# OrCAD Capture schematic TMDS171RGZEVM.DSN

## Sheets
1 P08:  TUSB3410: size B; title: TMDS171RGZEVM, TUSB3410; rev: A.0; company: Texas Instruments, CIS/ICP; note: GAGGIA.DSN
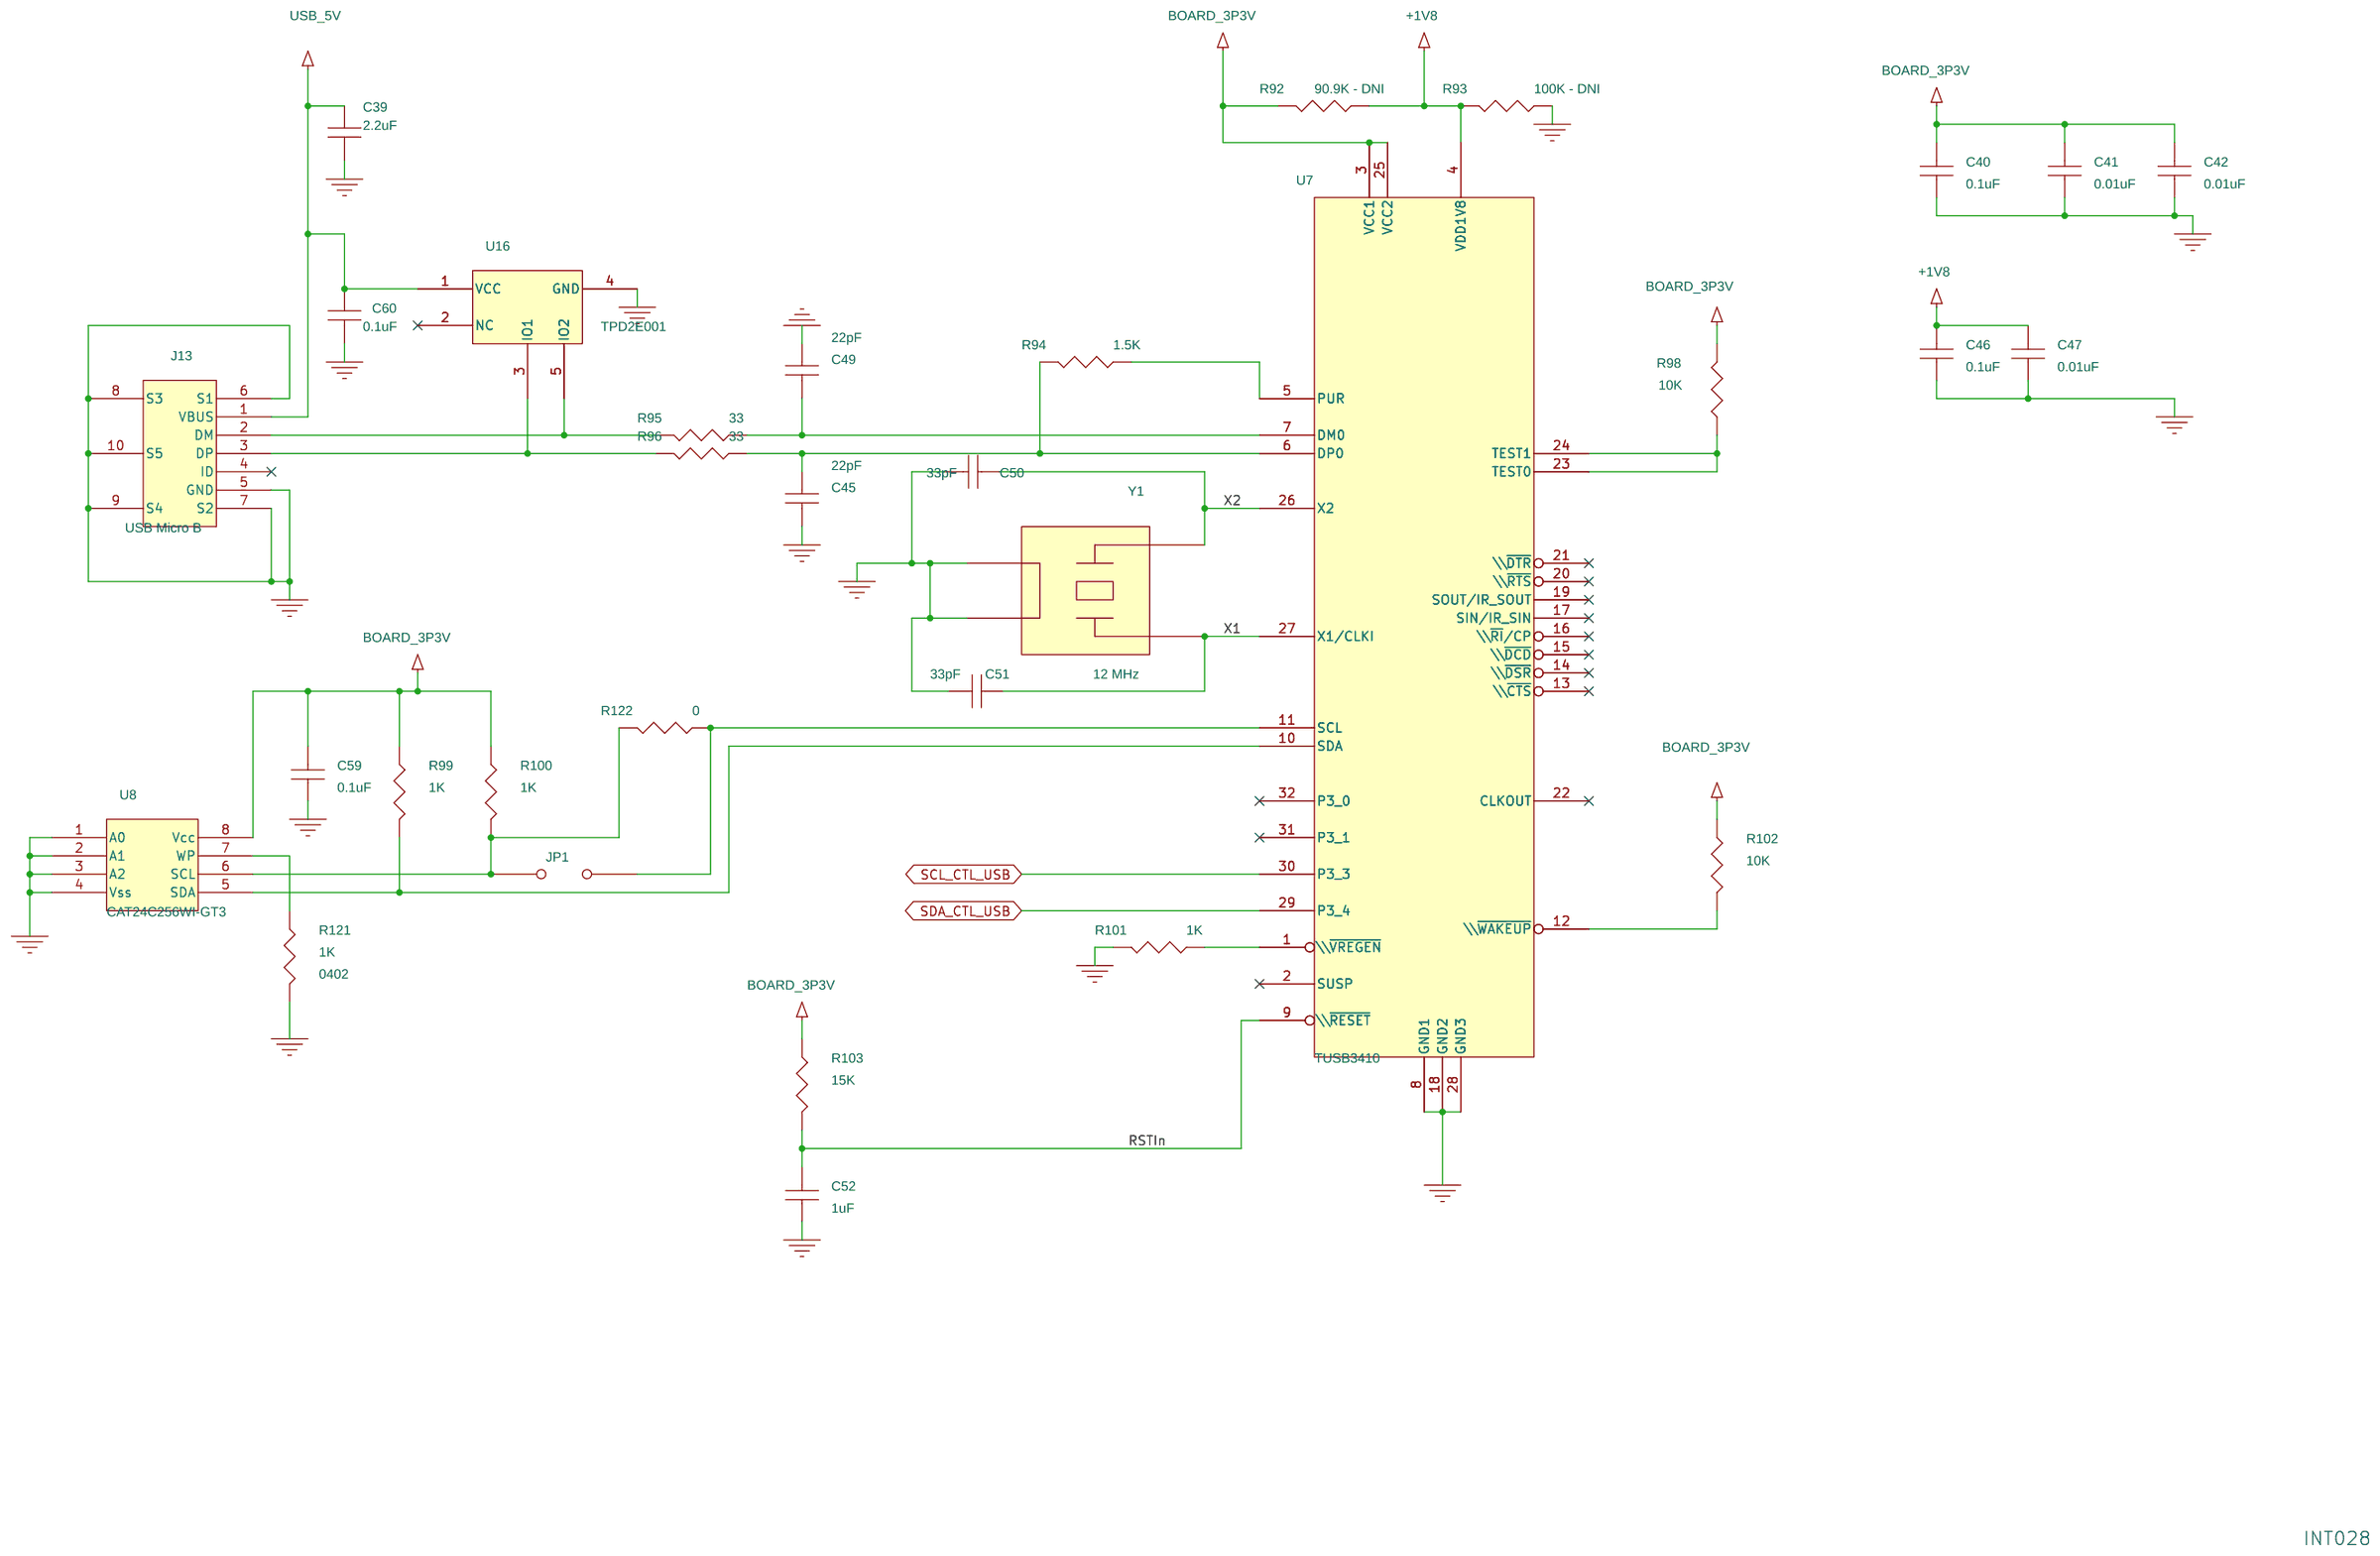
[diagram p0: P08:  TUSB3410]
2 P06:  RESET: size A; title: TMDS171RGZEVM, RESET
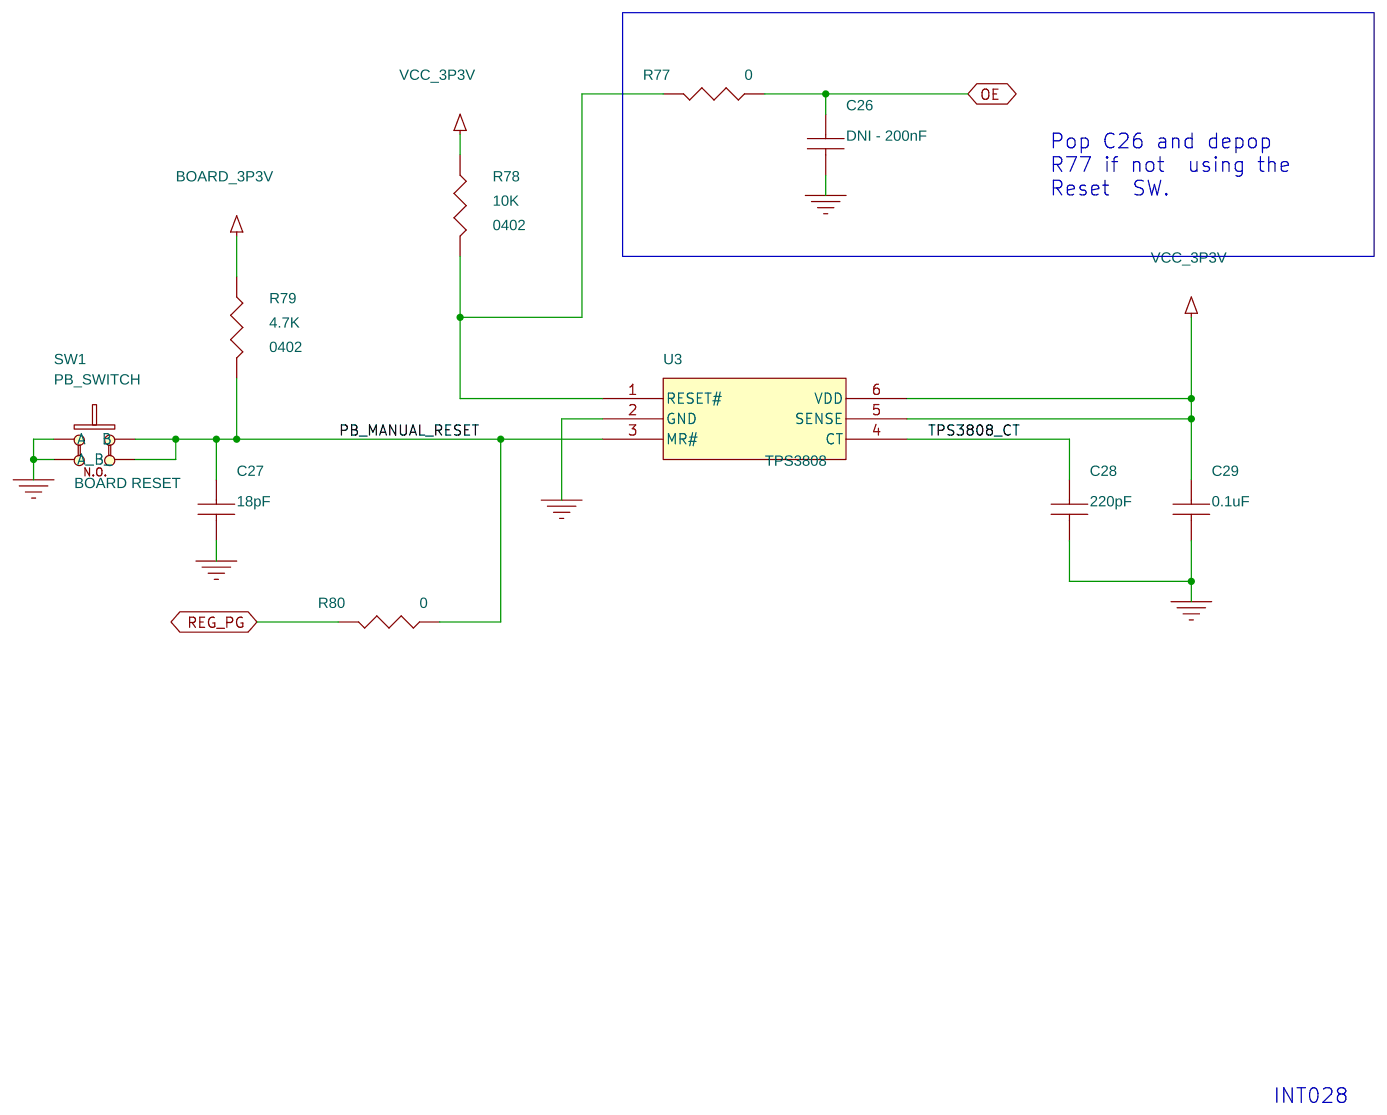
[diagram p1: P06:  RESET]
3 P01:  TITLE: size A; title: TMDS171RGZEVM
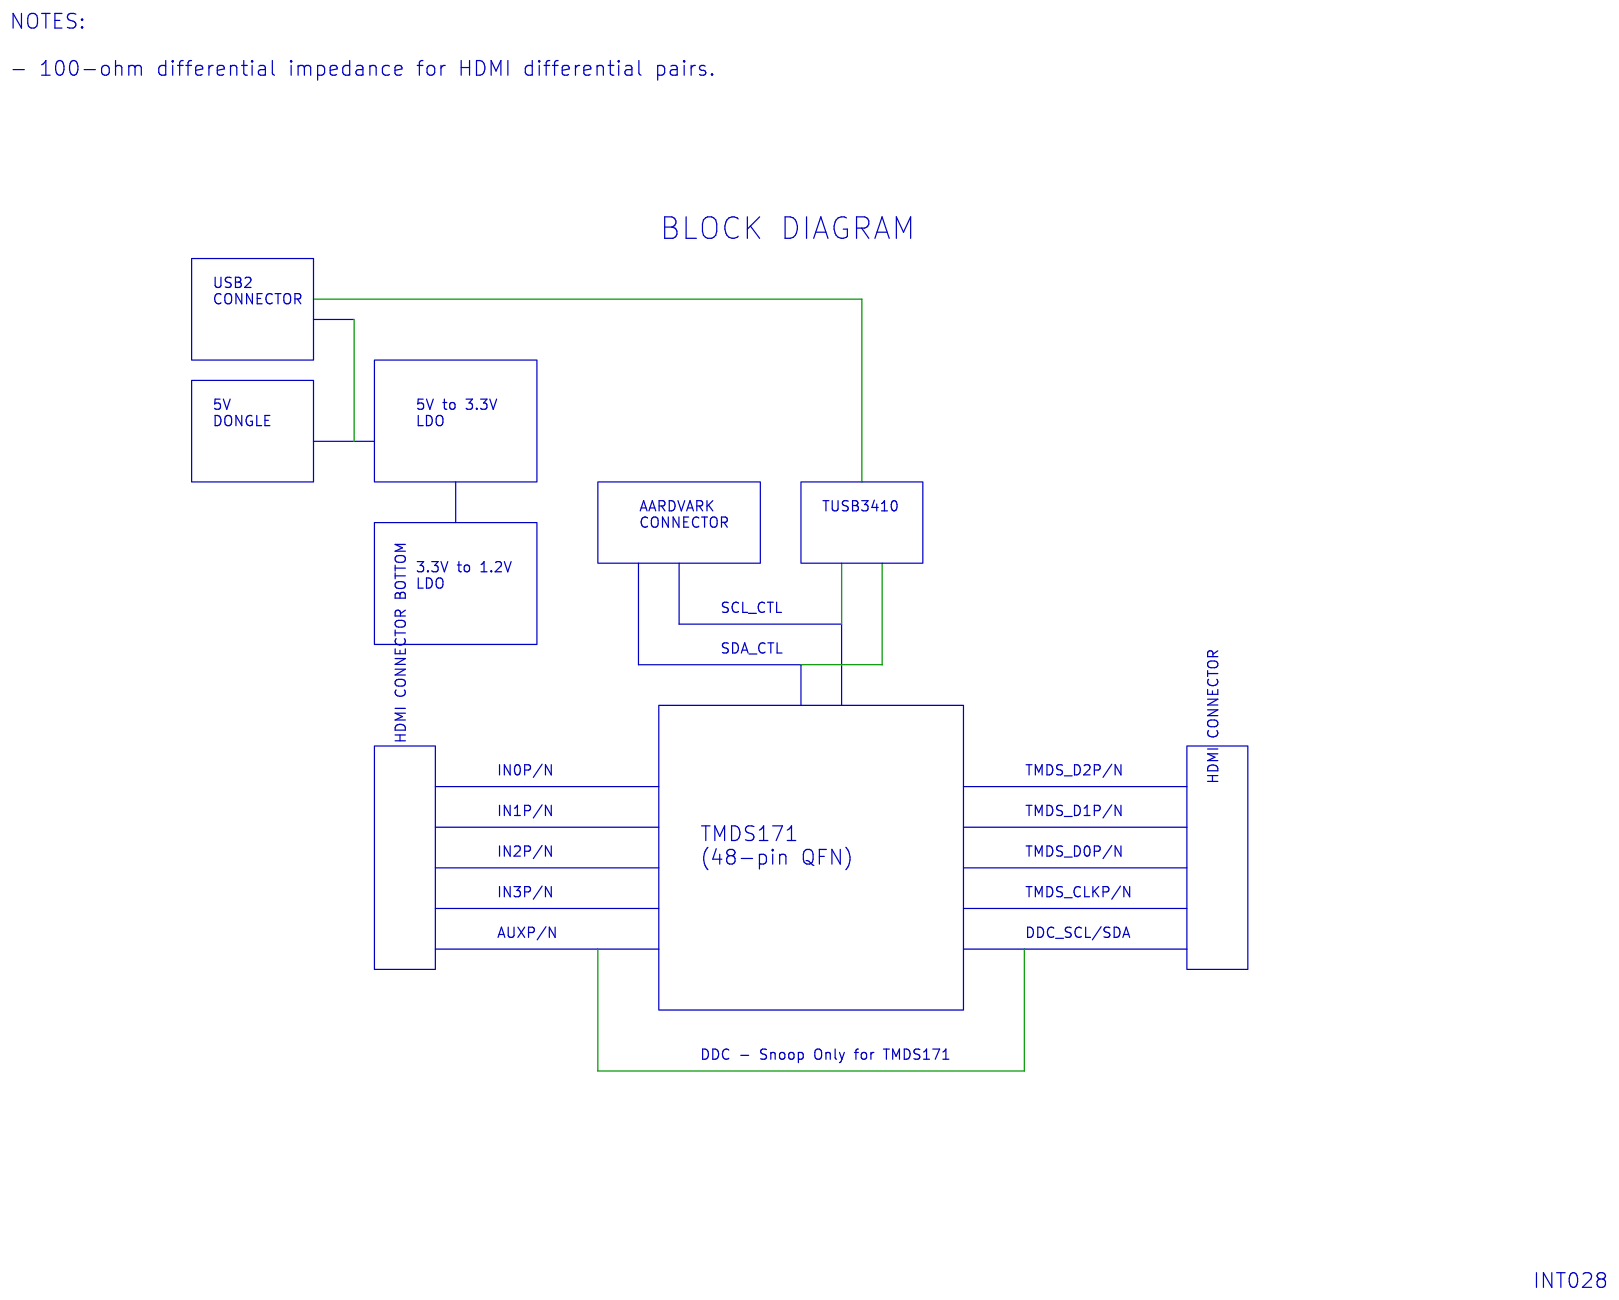
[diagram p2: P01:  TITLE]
4 P07:  POWER: size B; title: TMDS171RGZEVM, REGULATORS
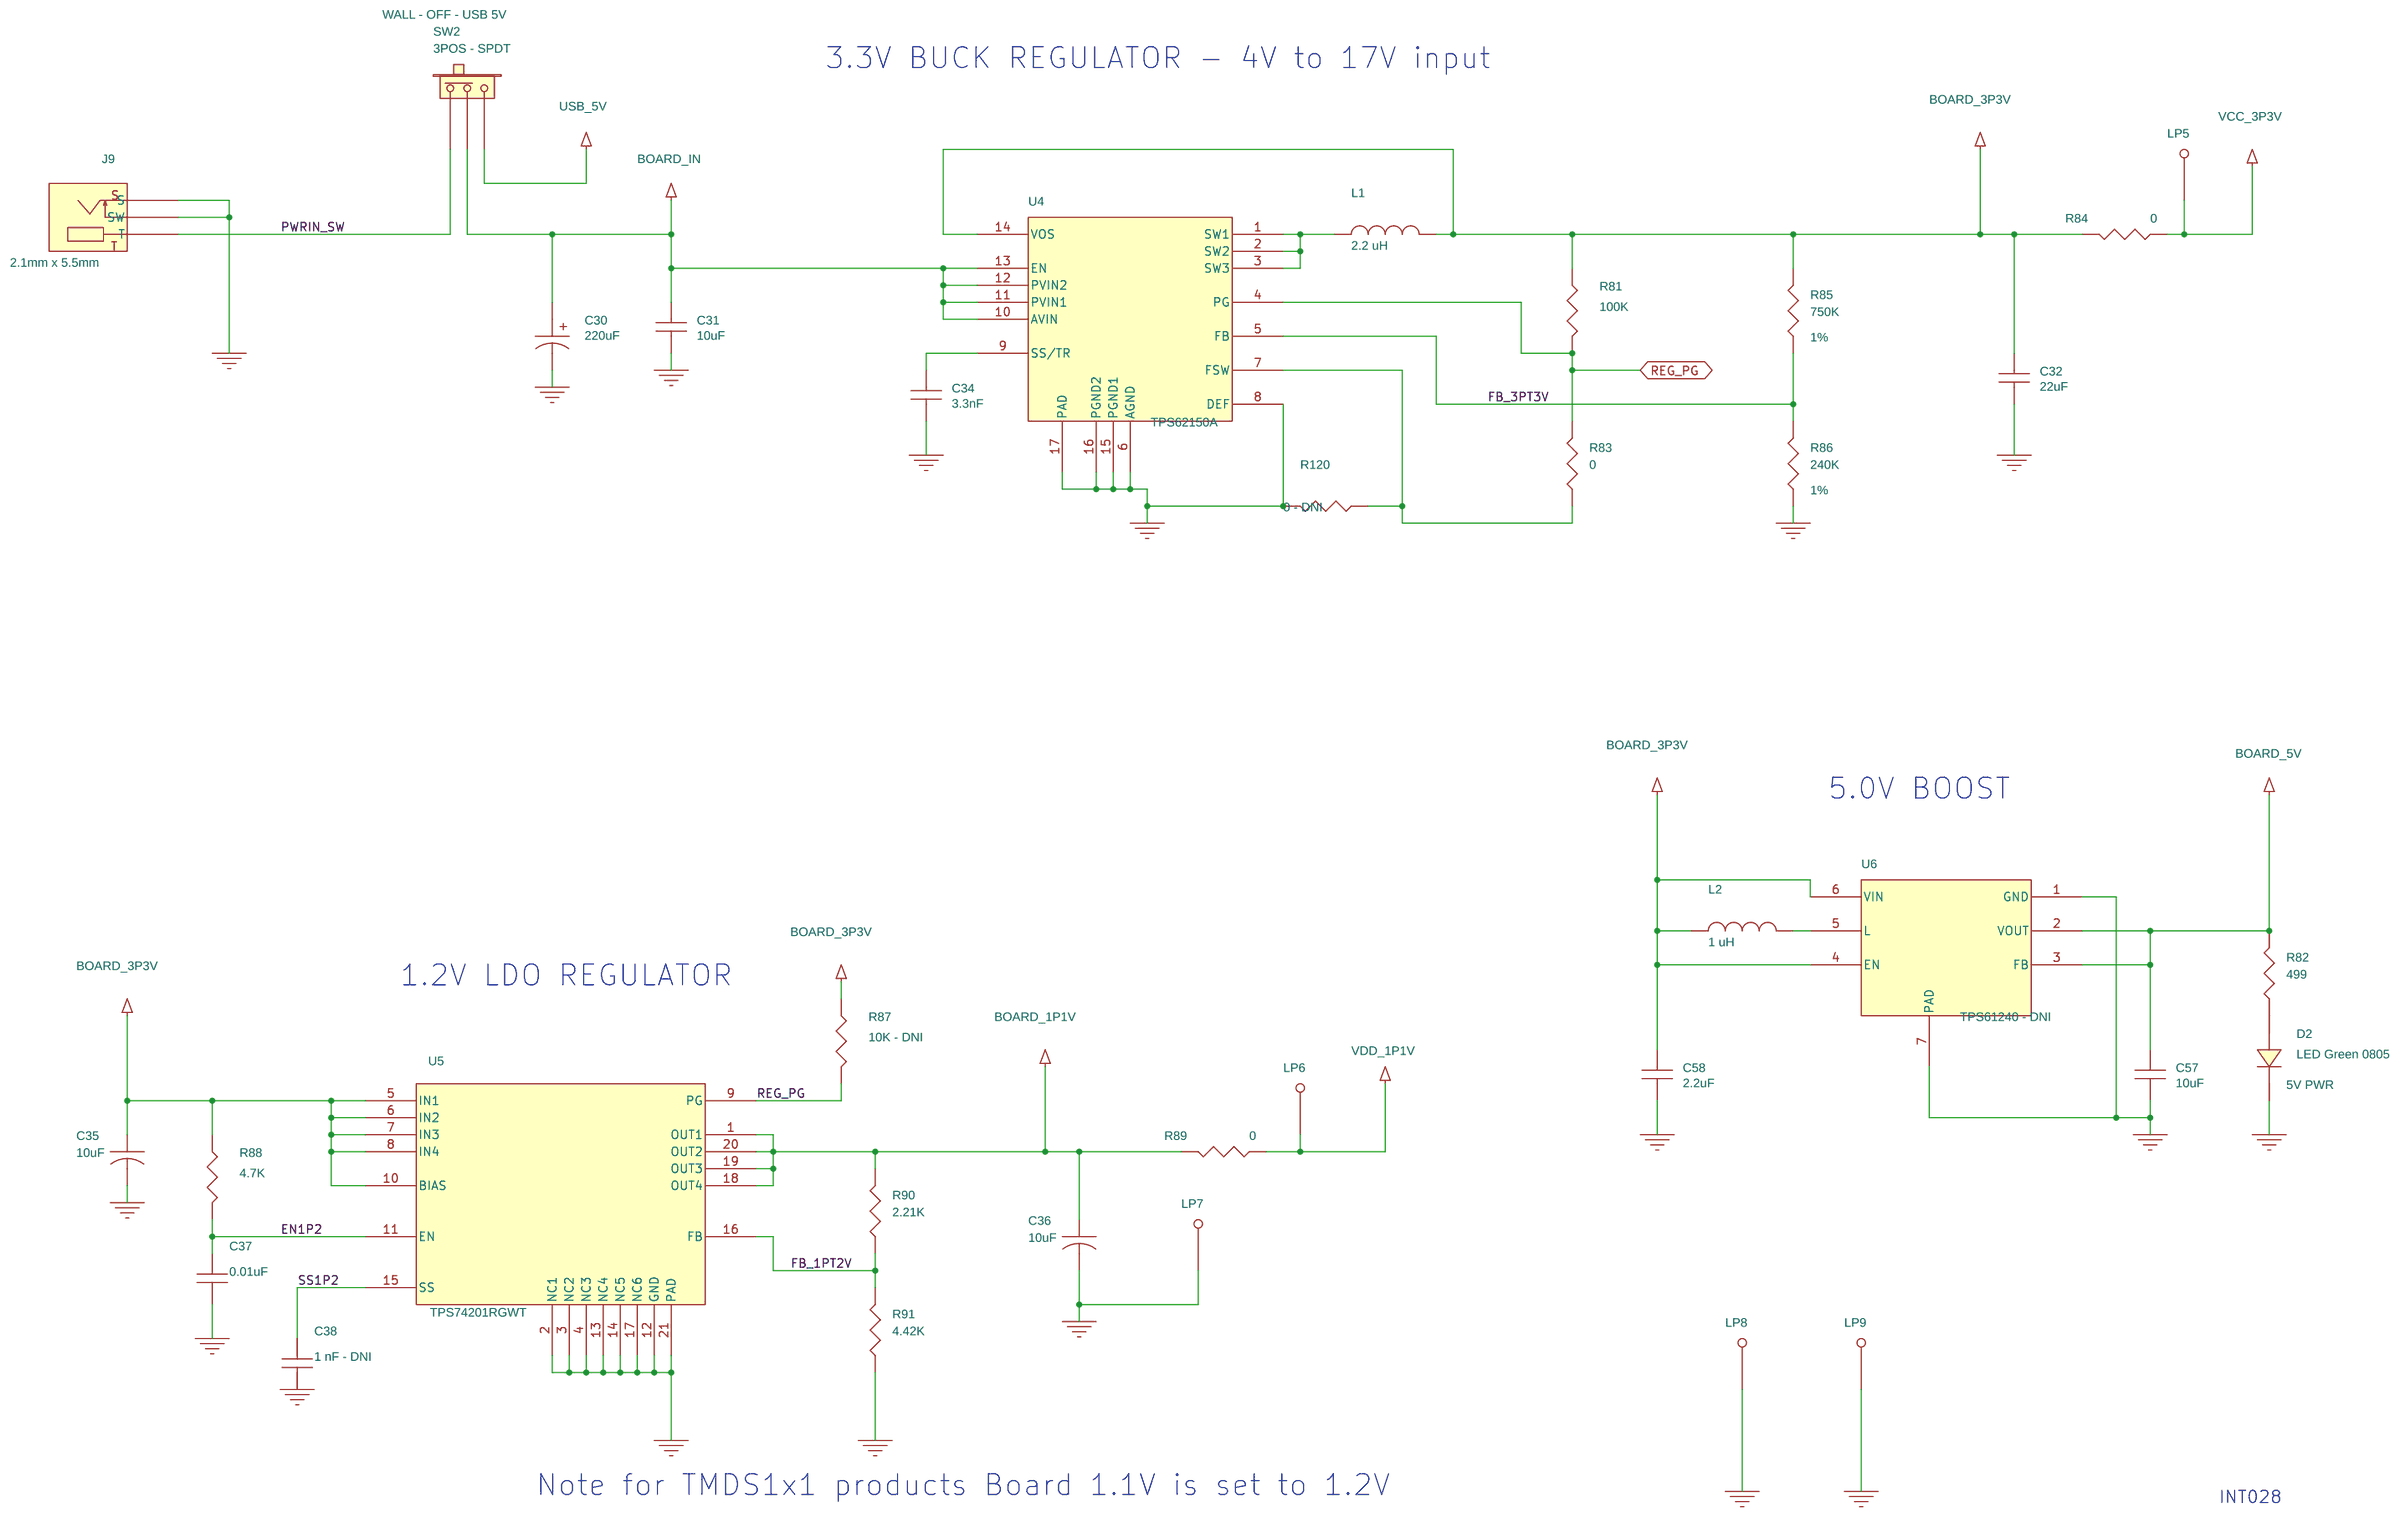
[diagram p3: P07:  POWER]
5 P04:  HDMI TX CONNECTOR: size A; title: TMDS171RGZEVM, HDMI OUTPUT
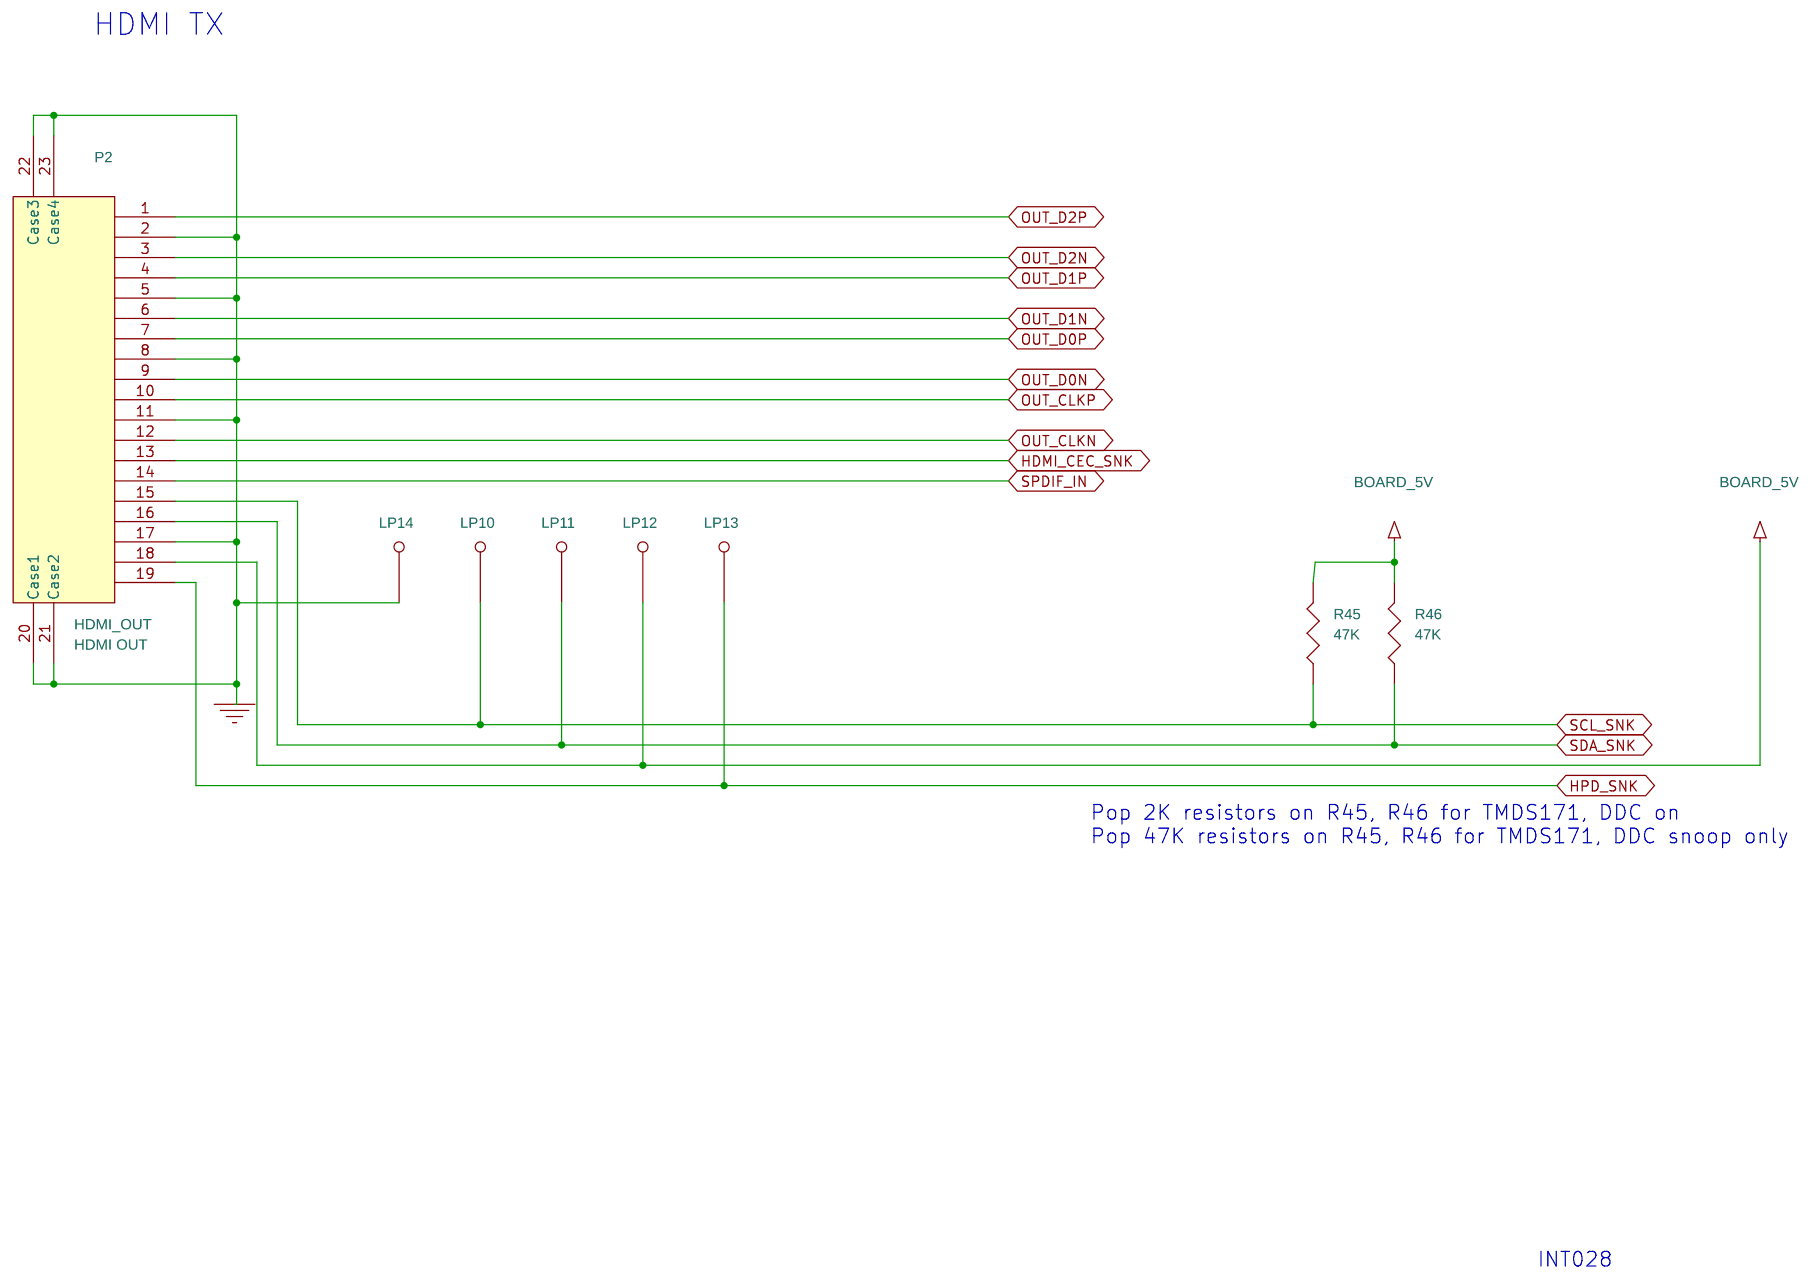
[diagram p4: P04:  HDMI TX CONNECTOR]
6 P03:  TMDS171RGZ: size B; title: TMDS171RGZEVM, TMDS171RGZ
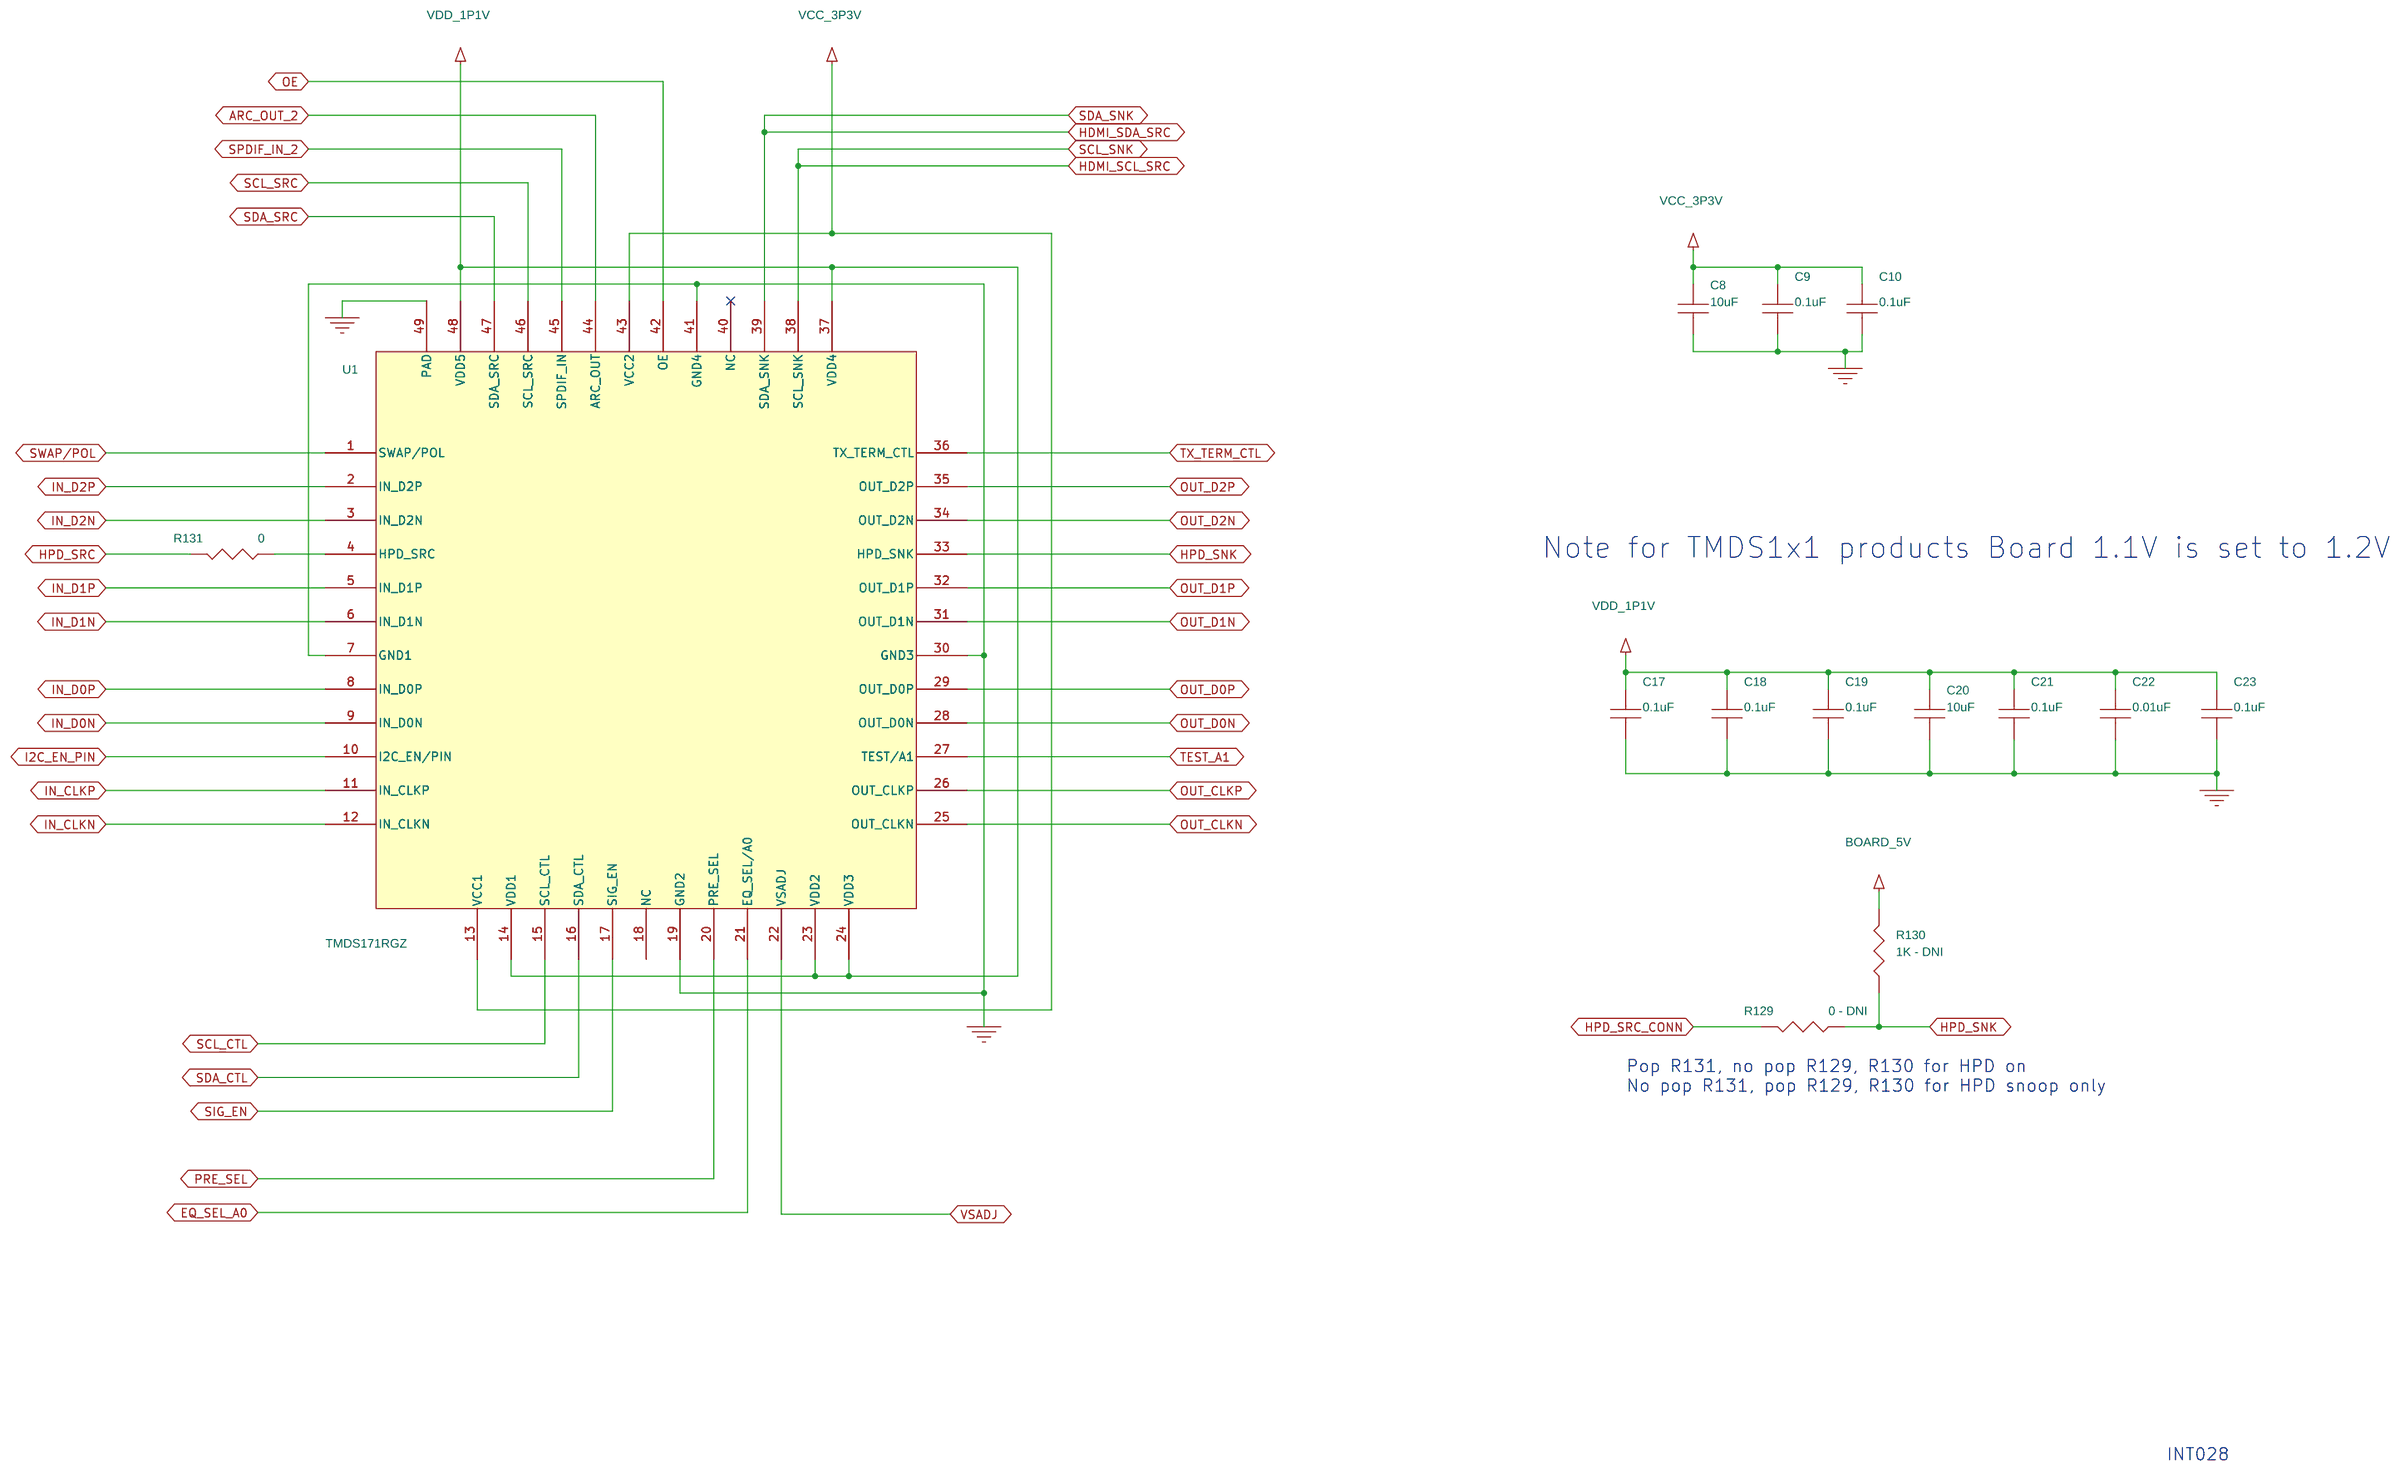
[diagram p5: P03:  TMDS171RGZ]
7 P05:  TMDS171 SEL OPTIONS: size B; title: TMDS171RGZEVM, SELECT OPTIONS
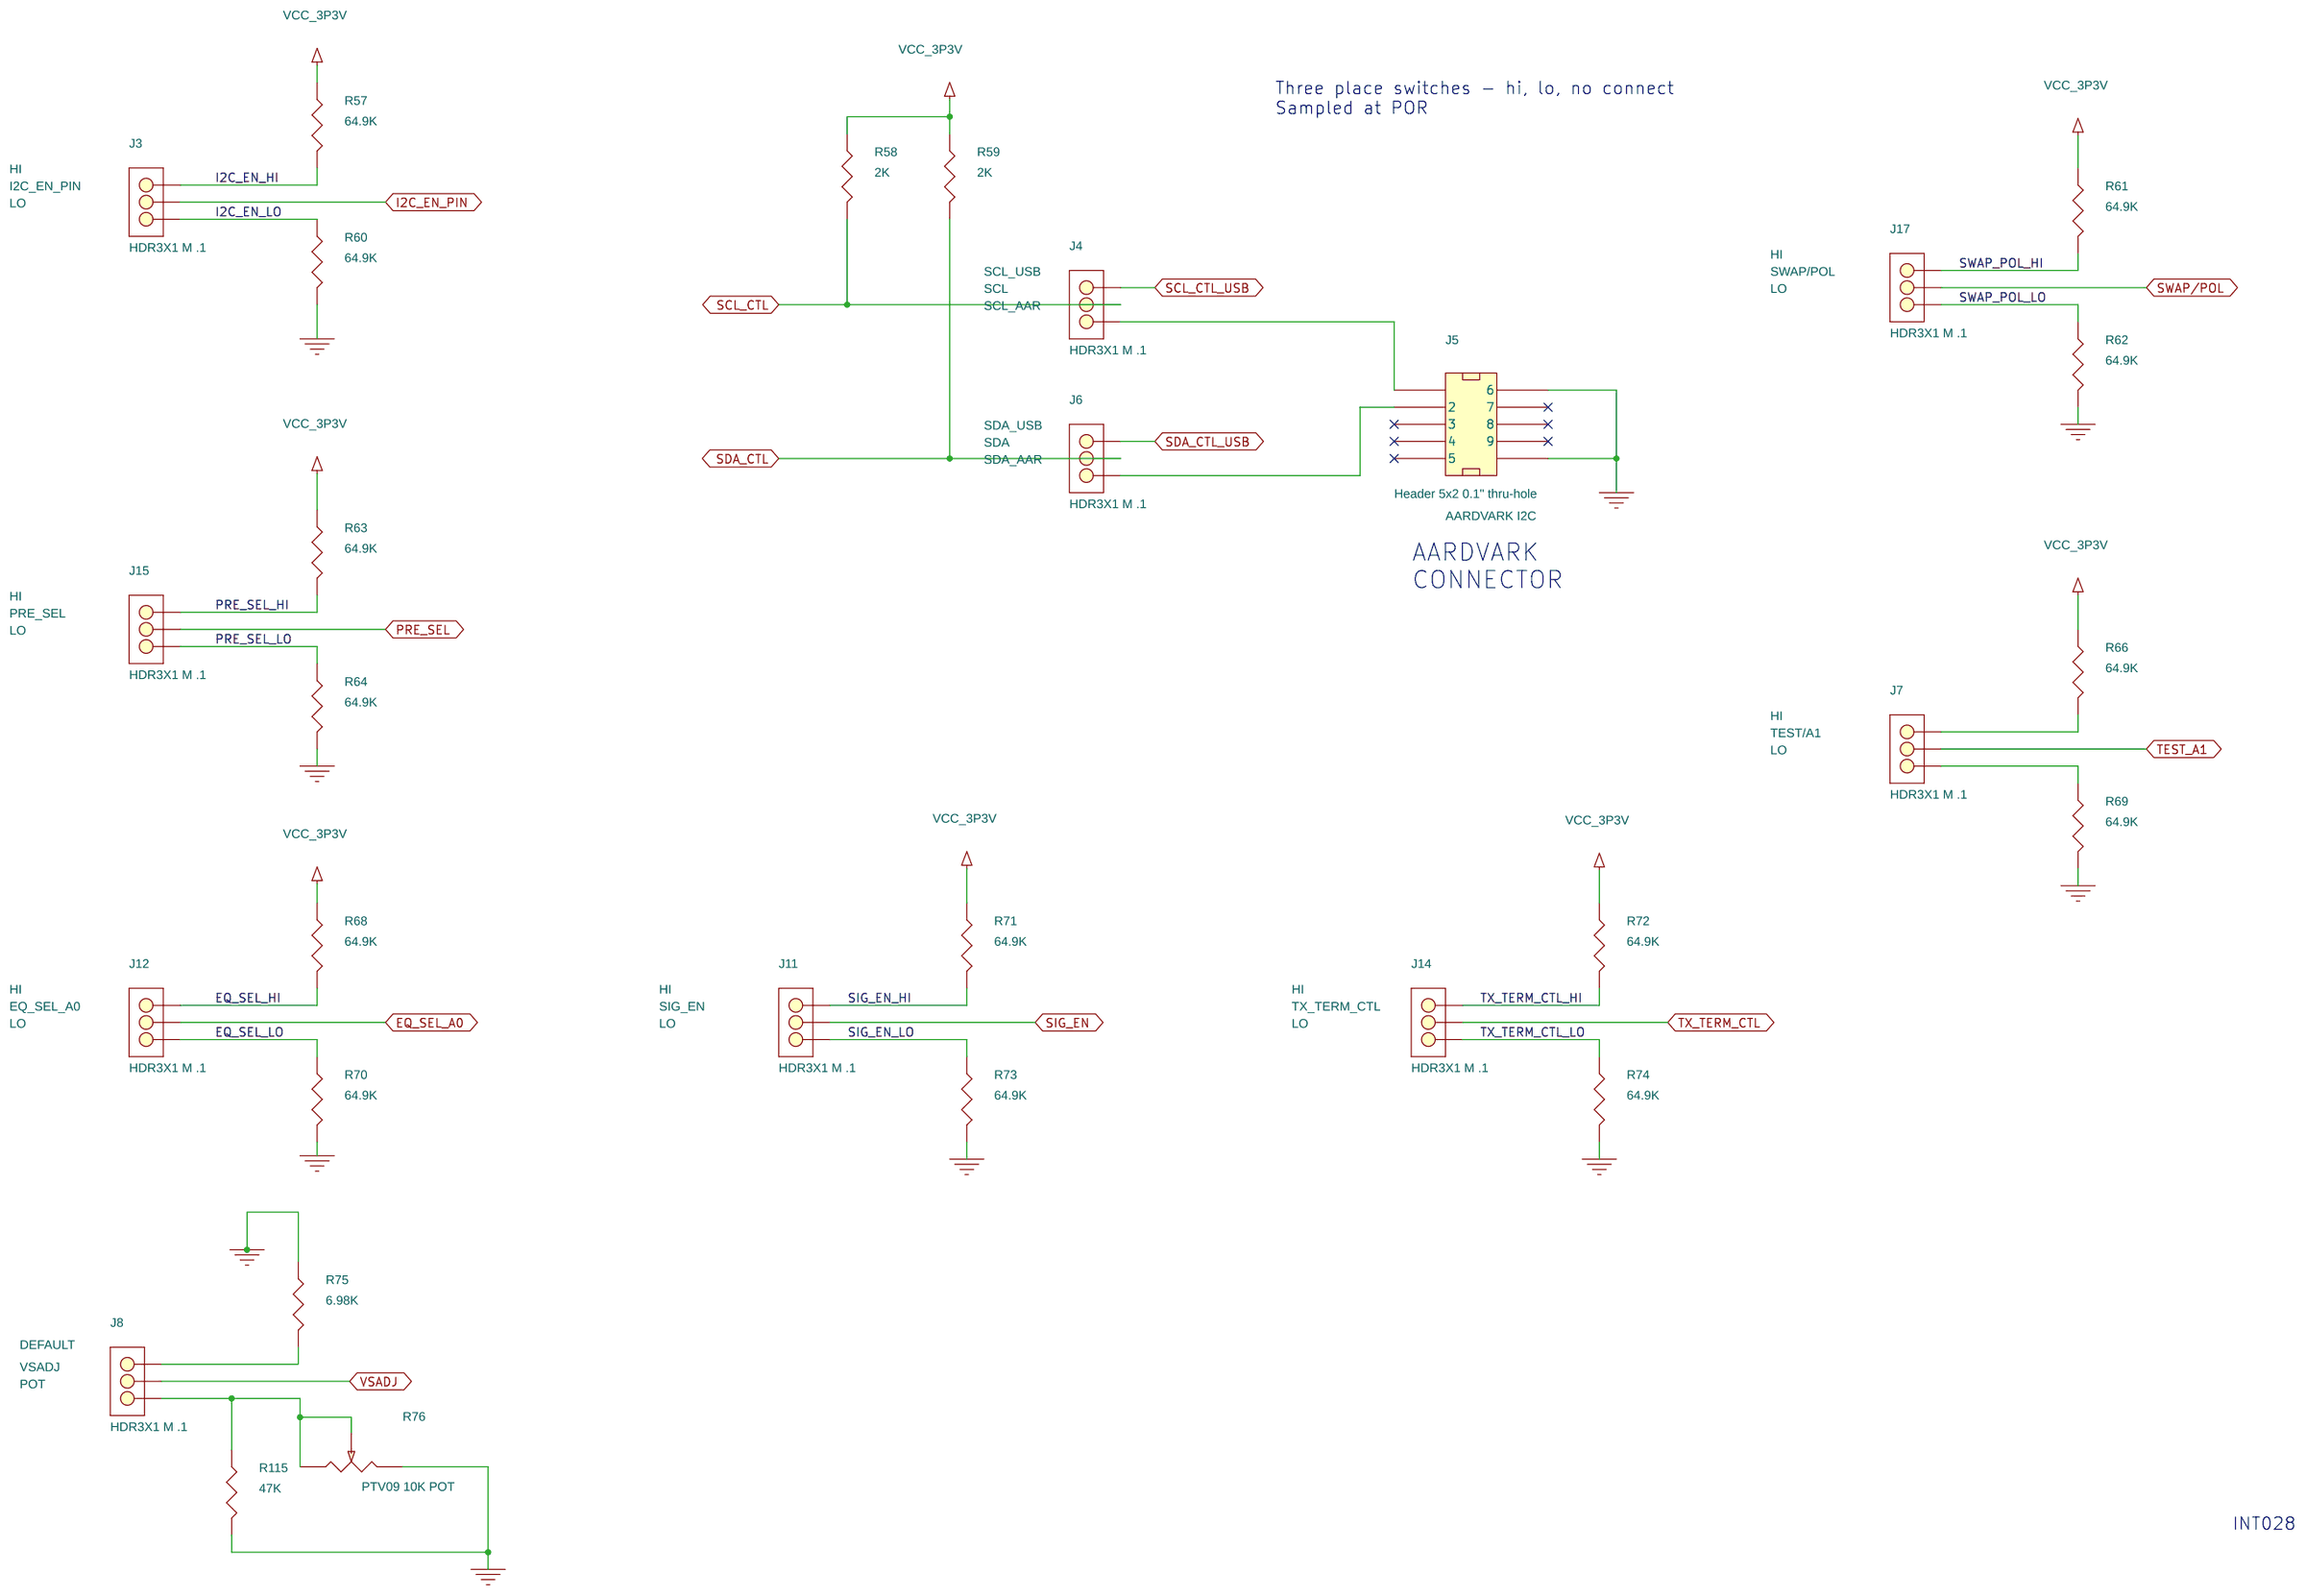
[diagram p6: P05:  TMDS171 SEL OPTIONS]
8 P02:  HDMI INPUT CONNECTOR: size B; title: TMDS171RGZEVM, HDMI INPUT
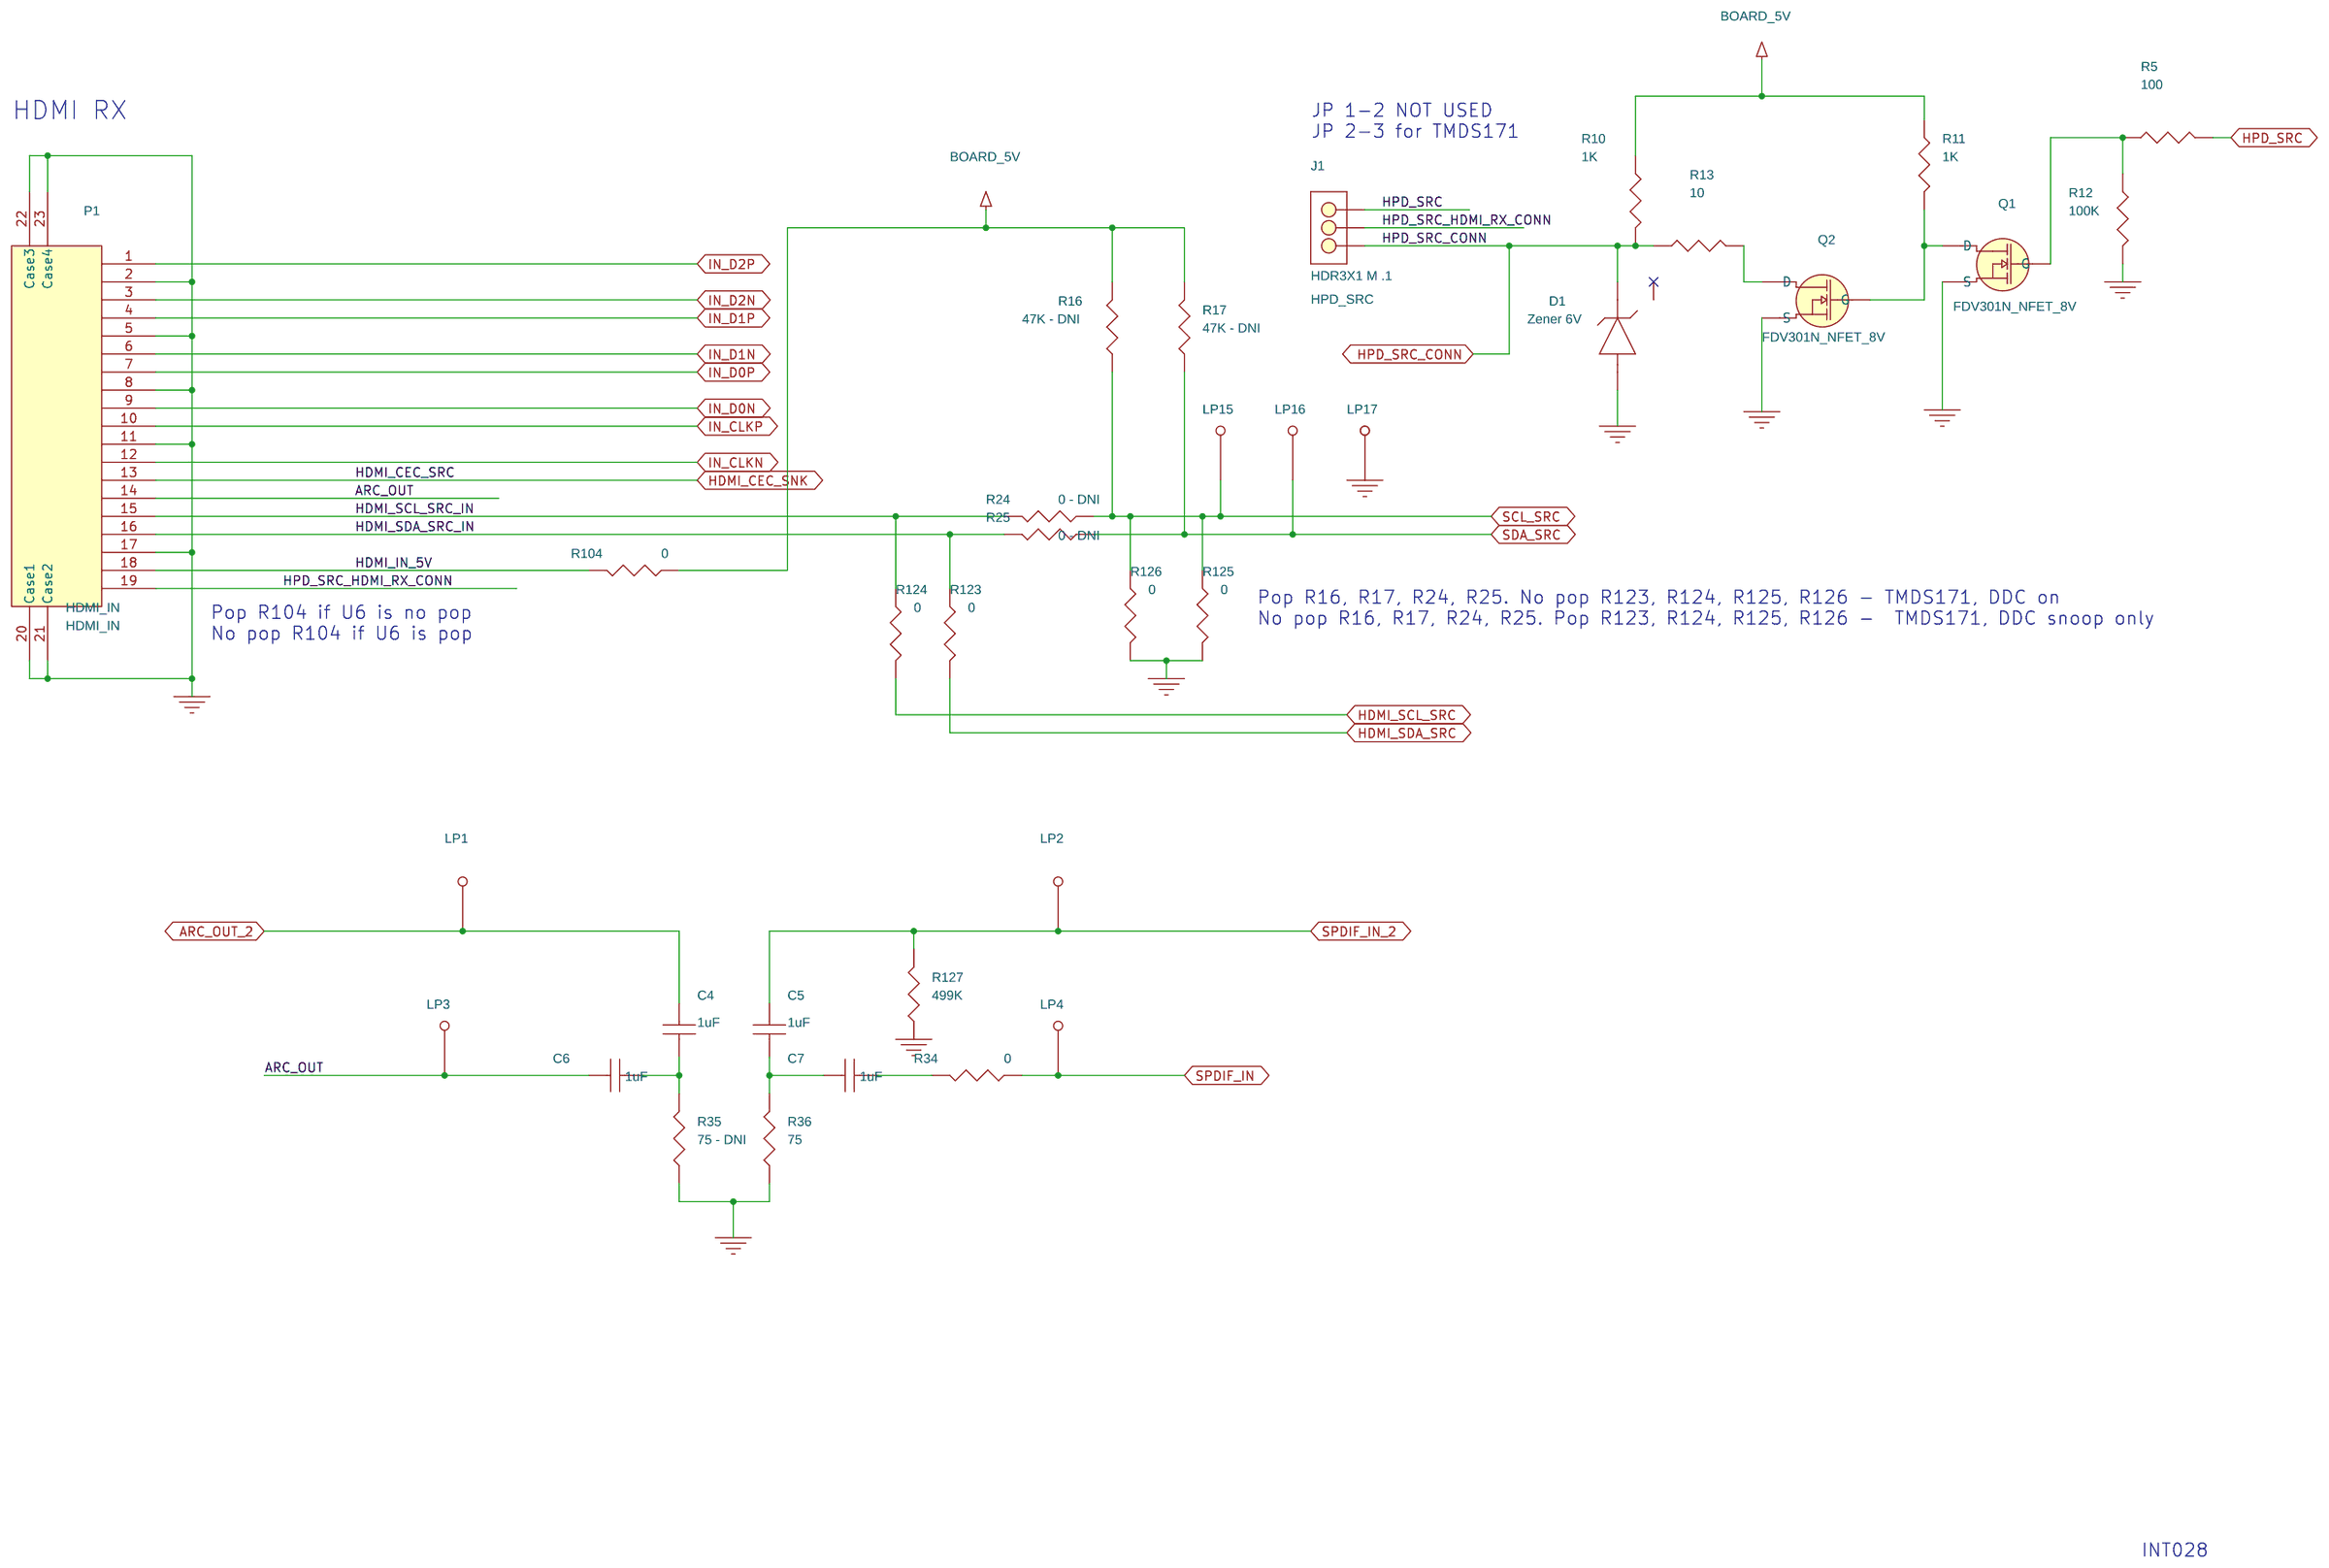
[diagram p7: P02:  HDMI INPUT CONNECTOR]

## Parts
sheet P02:  HDMI INPUT CONNECTOR
C4  1uF  [0603]
C5  1uF  [0603]
C6  1uF  [0603]
C7  1uF  [0603]
D1  Zener 6V  [SOT23]
J1  HDR3X1 M .1  [HDR_THVT_1x3_100]
LP1  LP  [TESTLOOP]
LP2  LP  [TESTLOOP]
LP3  LP  [TESTLOOP]
LP4  LP  [TESTLOOP]
LP15  LP
LP16  LP
LP17  LP
P1  HDMI_IN  [con_hdmi_SD-47151-001]
Q1  FDV301N_NFET_8V  [SOT23]
Q2  FDV301N_NFET_8V  [SOT23]
R5  100  [0402]
R10  1K  [0402]
R11  1K  [0402]
R12  100K  [0402]
R13  10  [0402]
R16  47K - DNI  [0402]
R17  47K - DNI  [0402]
R24  0 - DNI  [0201]
R25  0 - DNI  [0201]
R34  0  [0201]
R35  75 - DNI  [0402]
R36  75  [0402]
R104  0  [0402]
R123  0  [0201]
R124  0  [0201]
R125  0  [0201]
R126  0  [0201]
R127  499K  [0402]
sheet P03:  TMDS171RGZ
C8  10uF  [0805]
C9  0.1uF  [0402]
C10  0.1uF  [0402]
C17  0.1uF  [0402]
C18  0.1uF  [0402]
C19  0.1uF  [0402]
C20  10uF  [0805]
C21  0.1uF  [0402]
C22  0.01uF  [0402]
C23  0.1uF  [0402]
R129  0 - DNI  [0402]
R130  1K - DNI  [0402]
R131  0  [0402]
U1  TMDS171RGZ  [rgz48_gryphics_48qfn07-0p5]
sheet P04:  HDMI TX CONNECTOR
LP10  LP
LP11  LP
LP12  LP
LP13  LP
LP14  LP
P2  HDMI_OUT  [con_hdmi_SD-47151-001]
R45  47K  [0402]
R46  47K  [0402]
sheet P05:  TMDS171 SEL OPTIONS
J3  HDR3X1 M .1  [HDR_THVT_1x3_100]
J4  HDR3X1 M .1  [HDR_THVT_1x3_100]
J5  Header 5x2 0.1" thru-hole  [con_thvt_shrd_2x5_100_m]
J6  HDR3X1 M .1  [HDR_THVT_1x3_100]
J7  HDR3X1 M .1  [HDR_THVT_1x3_100]
J8  HDR3X1 M .1  [HDR_THVT_1x3_100]
J11  HDR3X1 M .1  [HDR_THVT_1x3_100]
J12  HDR3X1 M .1  [HDR_THVT_1x3_100]
J14  HDR3X1 M .1  [HDR_THVT_1x3_100]
J15  HDR3X1 M .1  [HDR_THVT_1x3_100]
J17  HDR3X1 M .1  [HDR_THVT_1x3_100]
R57  64.9K  [0402]
R58  2K  [0402]
R59  2K  [0402]
R60  64.9K  [0402]
R61  64.9K  [0402]
R62  64.9K  [0402]
R63  64.9K  [0402]
R64  64.9K  [0402]
R66  64.9K  [0402]
R68  64.9K  [0402]
R69  64.9K  [0402]
R70  64.9K  [0402]
R71  64.9K  [0402]
R72  64.9K  [0402]
R73  64.9K  [0402]
R74  64.9K  [0402]
R75  6.98K  [0402]
R76  PTV09 10K POT  [VAR_RES_THVT_PTV09A-1]
R115  47K  [0402]
sheet P06:  RESET
C26  DNI - 200nF  [0402]
C27  18pF  [0402]
C28  220pF  [0402]
C29  0.1uF  [0402]
R77  0  [0402]
R78  10K  [0402]
R79  4.7K  [0402]
R80  0  [0402]
SW1  PB_SWITCH  [SW_MOM_2NO]
U3  TPS3808  [DBV_R-PDSO-G6]
sheet P07:  POWER
C30  220uF  [7343]
C31  10uF  [0805]
C32  22uF  [0805]
C34  3.3nF  [0402]
C35  10uF  [0805]
C36  10uF  [0805]
C37  0.01uF  [0402]
C38  1 nF - DNI  [0402]
C57  10uF  [0805]
C58  2.2uF  [0805]
D2  LED Green 0805  [0805]
J9  2.1mm x 5.5mm  [PJ-202AH]
L1  2.2 uH  [IND_1008]
L2  1 uH  [IND_1008]
LP5  LP  [TESTLOOP]
LP6  LP  [TESTLOOP]
LP7  LP  [TESTLOOP]
LP8  LP  [TESTLOOP]
LP9  LP  [TESTLOOP]
R81  100K  [0402]
R82  499  [0402]
R83  0  [0402]
R84  0  [0402]
R85  750K  [0402]
R86  240K  [0402]
R87  10K - DNI  [0402]
R88  4.7K  [0402]
R89  0  [0402]
R90  2.21K  [0402]
R91  4.42K  [0402]
R120  0 - DNI  [0402]
SW2  3POS - SPDT  [sw_thvt_spdt_3_185p]
U4  TPS62150A  [RGT_QFN-16]
U5  TPS74201RGWT  [QFN_20_203x203_26]
U6  TPS61240 - DNI  [DRV_S-PWSON-N6]
sheet P08:  TUSB3410
C39  2.2uF  [0805]
C40  0.1uF  [0402]
C41  0.01uF  [0402]
C42  0.01uF  [0402]
C45  22pF  [0402]
C46  0.1uF  [0402]
C47  0.01uF  [0402]
C49  22pF  [0402]
C50  33pF  [0402]
C51  33pF  [0402]
C52  1uF  [0603]
C59  0.1uF  [0402]
C60  0.1uF  [0402]
J13  USB Micro B  [usb_micro_b_fci]
JP1  JUMPER  [HDR_THVT_1x2_100]
R92  90.9K - DNI  [0402]
R93  100K - DNI  [0402]
R94  1.5K  [0402]
R95  33  [0201]
R96  33  [0201]
R98  10K  [0402]
R99  1K  [0402]
R100  1K  [0402]
R101  1K  [0402]
R102  10K  [0402]
R103  15K  [0402]
R121  1K  [0402]
R122  0  [0402]
U7  TUSB3410  [PQFP_32_7P2X7P2_P8MM]
U8  CAT24C256WI-GT3  [soic_8_197x157_50]
U16  TPD2E001  [drl_5pin]
Y1  12 MHz  [XTAL_4_SM_126X98]

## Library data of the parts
C4-C10 C17-C23 C26-C29 C31 C32 C34 C37-C42 C45-C47 C49 C52 C57-C60 = CAP_NP
D1 = Zener_6V
J1 = HDR3X1_M__2.1: SILKTEXT2: HPD_SRC
LP1-LP9 = TESTLOOP: Manuf: KOBIKONN; Manuf PN: 151-103-RC
LP10-LP17 = TESTLOOP
P1 = CONN_HDMI_TYPE_A: Manuf: Molex; Manuf PN: 500254-1927
Q1 Q2 = FDV301N_NFET_8V
R5 R10-R13 = r0402
R16 R17 R24 R25 R34-R36 R45 R46 R57 R61-R64 R66 R68-R74 R77-R81 R84 R87 R89 R92-R96 R98-R104 R115 R121-R127 R129-R131 = R: Tolerance: 5%
U1 = DP159RGZ_10: SILKTEXT: 48 PIN RGZ, HSIO
P2 = CONN_HDMI_TYPE_A: Manuf: Molex; Manuf PN: 500254-1927; SILKTEXT: HDMI OUT
J3 = HDR3X1_M__2.1: SILKTEXT1: HI; SILKTEXT2: I2C_EN_PIN; SILKTEXT3: LO
J4 = HDR3X1_M__2.1: SILKTEXT1: SCL_USB; SILKTEXT2: SCL; SILKTEXT3: SCL_AAR
J5 = CONN_PCB_5x2-S: Manuf: 3M; Manuf PN: N2510-6002-RB; SILKTEXT: AARDVARK I2C
J6 = HDR3X1_M__2.1: SILKTEXT1: SDA_USB; SILKTEXT2: SDA; SILKTEXT3: SDA_AAR
J7 = HDR3X1_M__2.1: SILKTEXT1: HI; SILKTEXT2: TEST/A1; SILKTEXT3: LO
J8 = HDR3X1_M__2.1: SILKTEXT1: DEFAULT; SILKTEXT2: VSADJ; SILKTEXT3: POT
J11 = HDR3X1_M__2.1: SILKTEXT1: HI; SILKTEXT2: SIG_EN; SILKTEXT3: LO
J12 = HDR3X1_M__2.1: SILKTEXT1: HI; SILKTEXT2: EQ_SEL_A0; SILKTEXT3: LO
J14 = HDR3X1_M__2.1: SILKTEXT1: HI; SILKTEXT2: TX_TERM_CTL; SILKTEXT3: LO
J15 = HDR3X1_M__2.1: SILKTEXT1: HI; SILKTEXT2: PRE_SEL; SILKTEXT3: LO
J17 = HDR3X1_M__2.1: SILKTEXT1: HI; SILKTEXT2: SWAP/POL; SILKTEXT3: LO
R58-R60 R82 R88 = R_4: Tolerance: 5%
R75 R83 R85 R86 R120 = R: Tolerance: 1%
R76 = POT
SW1 = PB_SWITCH_0: Manuf: OMRON; Manuf PN: B3SN-3012P; Part#: B3SN-3012P; SILKTEXT: BOARD RESET
U3 = TPS3808DBV: Manuf PN: TPS3808G30DBVT
C30 = CAPACITOR_POL: Manuf: Kemet; Manuf PN: T495X337K010ATE060
C35 C36 = CAP_0: CAP CER 10UF 6.3V 10% X5R 0805; Mfr: MURATA; PN: GRM21BR60J106KE19L; TN: 207-0208-000
D2 = DIODE: SILKTEXT: 5V PWR
J9 = BNC_2: MANUF: CUI STACK; PART_NUMBER: 5V_SUPPLY; SILKTEXT: 5V ONLY!
L1 L2 = INDUCTOR
R90 R91 = R_4: Tolerance: 1%
SW2 = SW_SLIDE_SPDT2: Manuf: NKK Switches; Manuf PN: MS13ANW03; Manufacturer: NKK Switches; Manufacturer's Part Number: MS13ANW03; Part_Type: Switch\Slide; SILKTEXT: WALL - OFF - USB 5V
U4 = TPS62150A
U5 = TPS74401RGWT_1
U6 = TPS61420
C50 C51 = CAP_NP: Vendor: Digi-Key
J13 = USB_Mini_AB_0: PN: 10103592-0001LF; TYPE: MOLEX MICRO AB
JP1 = JUMPER
U7 = TUSB3410_3: Vendor: T.I.
U8 = I2C_0: Vendor: Digi-Key
U16 = TPD2E001-Q1
Y1 = CRYSTAL14_0

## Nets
+1V8: C46.2 C47.2 R92.1 R93.2 U7.4(VDD1V8)
GND: C8.2 C9.2 C10.2 C17.2 C18.2 C19.2 C20.2 C21.2 C22.2 C23.2 C26.2 C27.2 C28.2 C29.2 C30.2 C31.2 C32.2 C34.2 C35.2 C36.2 C37.2 C38.2 C39.2 C40.1 C41.1 C42.1 C45.2 C46.1 C47.1 C49.1 C50.2 C51.2 C52.1 C57.2 C58.2 C59.1 C60.2 D1.1 D2.2(K) J5.2(6) J5.10 J9.2(S) J9.3(SW) J13.5(GND) J13.6(S1) J13.7(S2) J13.8(S3) J13.9(S4) J13.10(S5) LP7.1 LP8.1 LP9.1 LP14.1 LP17.1 P1.2 P1.5 P1.8 P1.11 P1.17 P1.20(Case1) P1.21(Case2) P1.22(Case3) P1.23(Case4) P2.2 P2.5 P2.8 P2.11 P2.17 P2.20(Case1) P2.21(Case2) P2.22(Case3) P2.23(Case4) Q1.2(S) Q2.2(S) R12.1 R35.1 R36.1 R60.2 R62.2 R64.2 R69.2 R70.2 R73.2 R74.2 R75.1 R76.3(B) R86.1 R91.1 R93.1 R101.2 R115.2 R120.2 R121.2 R125.2 R126.2 R127.1 SW1.1(A) SW1.2(A_) U1.7(GND1) U1.19(GND2) U1.30(GND3) U1.41(GND4) U1.49(PAD) U3.2(GND) U4.6(AGND) U4.8(DEF) U4.15(PGND1) U4.16(PGND2) U4.17(PAD) U5.2(NC1) U5.3(NC2) U5.4(NC3) U5.12(GND) U5.13(NC4) U5.14(NC5) U5.17(NC6) U5.21(PAD) U6.1(GND) U6.7(PAD) U7.8(GND1) U7.18(GND2) U7.28(GND3) U8.1(A0) U8.2(A1) U8.3(A2) U8.4(Vss) U16.4(GND) Y1.2 Y1.4
VCC_3P3V: C8.1 C9.1 C10.1 C29.1 LP5.1 R57.1 R58.1 R59.1 R61.1 R63.1 R66.1 R68.1 R71.1 R72.1 R78.1 R84.1 U1.13(VCC1) U1.43(VCC2) U3.5(SENSE) U3.6(VDD)
VDD_1P1V: C17.1 C18.1 C19.1 C20.1 C21.1 C22.1 C23.1 LP6.1 R89.1 U1.14(VDD1) U1.23(VDD2) U1.24(VDD3) U1.37(VDD4) U1.48(VDD5)
ARC_OUT: C6.1 LP3.1 P1.14
ARC_OUT_2: C4.1 LP1.1 U1.44(ARC_OUT)
BOARD_1P1V: C36.1 R89.2 R90.2 U5.1(OUT1) U5.18(OUT4) U5.19(OUT3) U5.20(OUT2)
BOARD_3P3V: C32.1 C35.1 C40.2 C41.2 C42.2 C58.1 C59.2 L1.2 L2.1 R79.1 R81.1 R84.2 R85.2 R87.1 R88.1 R92.2 R98.1 R99.1 R100.1 R102.1 R103.1 U4.14(VOS) U5.5(IN1) U5.6(IN2) U5.7(IN3) U5.8(IN4) U5.10(BIAS) U6.4(EN) U6.6(VIN) U7.3(VCC1) U7.25(VCC2) U8.8(Vcc)
BOARD_5V: C57.1 LP12.1 P2.18 R10.2 R11.2 R16.2 R17.2 R45.2 R46.2 R82.2 R104.1 R130.2 U6.2(VOUT) U6.3(FB)
BOARD_IN: C30.1 C31.1 SW2.2 U4.10(AVIN) U4.11(PVIN1) U4.12(PVIN2) U4.13(EN)
EN1P2: C37.1 R88.2 U5.11(EN)
EQ_SEL_A0: J12.2 U1.21(EQ_SEL/A0)
EQ_SEL_HI: J12.1 R68.2
EQ_SEL_LO: J12.3 R70.1
FB_1PT2V: R90.1 R91.2 U5.16(FB)
FB_3PT3V: R85.1 R86.2 U4.5(FB)
HDMI_CEC_SNK: P1.13 P2.13
HDMI_IN_5V: P1.18 R104.2
HDMI_SCL_SRC: LP10.1 P2.15 R45.1 R124.2 U1.38(SCL_SNK)
HDMI_SCL_SRC_IN: P1.15 R24.2 R124.1
HDMI_SDA_SRC: LP11.1 P2.16 R46.1 R123.2 U1.39(SDA_SNK)
HDMI_SDA_SRC_IN: P1.16 R25.2 R123.1
HPD_SNK: LP13.1 P2.19 R129.1 R130.1 U1.33(HPD_SNK)
HPD_SRC: J1.1 R5.1 R131.2
HPD_SRC_CONN: D1.3 J1.3 R10.1 R13.2 R129.2
HPD_SRC_HDMI_RX_CONN: J1.2 P1.19
I2C_EN_HI: J3.1 R57.2
I2C_EN_LO: J3.3 R60.1
I2C_EN_PIN: J3.2 U1.10(I2C_EN/PIN)
IN_CLKN: P1.12 U1.12(IN_CLKN)
IN_CLKP: P1.10 U1.11(IN_CLKP)
IN_D0N: P1.9 U1.9(IN_D0N)
IN_D0P: P1.7 U1.8(IN_D0P)
IN_D1N: P1.6 U1.6(IN_D1N)
IN_D1P: P1.4 U1.5(IN_D1P)
IN_D2N: P1.3 U1.3(IN_D2N)
IN_D2P: P1.1 U1.2(IN_D2P)
OE: C26.1 R77.1 U1.42(OE)
OUT_CLKN: P2.12 U1.25(OUT_CLKN)
OUT_CLKP: P2.10 U1.26(OUT_CLKP)
OUT_D0N: P2.9 U1.28(OUT_D0N)
OUT_D0P: P2.7 U1.29(OUT_D0P)
OUT_D1N: P2.6 U1.31(OUT_D1N)
OUT_D1P: P2.4 U1.32(OUT_D1P)
OUT_D2N: P2.3 U1.34(OUT_D2N)
OUT_D2P: P2.1 U1.35(OUT_D2P)
PB_MANUAL_RESET: C27.1 R79.2 R80.1 SW1.3(B_) SW1.4(B) U3.3(MR#)
PRE_SEL: J15.2 U1.20(PRE_SEL)
PRE_SEL_HI: J15.1 R63.2
PRE_SEL_LO: J15.3 R64.1
PWRIN_SW: J9.1(T) SW2.1
REG_PG: R80.2 R81.2 R83.2 R87.2 U4.4(PG) U5.9(PG)
RSTIn: C52.2 R103.2 U7.9(\\~{RESET})
SCL_CTL: J4.2 R58.2 U1.15(SCL_CTL)
SCL_CTL_USB: J4.1 U7.30(P3_3)
SCL_SRC: LP15.1 R16.1 R24.1 R125.1 R126.1 U1.46(SCL_SRC)
SDA_CTL: J6.2 R59.2 U1.16(SDA_CTL)
SDA_CTL_USB: J6.1 U7.29(P3_4)
SDA_SRC: LP16.1 R17.1 R25.1 U1.47(SDA_SRC)
SIG_EN: J11.2 U1.17(SIG_EN)
SIG_EN_HI: J11.1 R71.2
SIG_EN_LO: J11.3 R73.1
SPDIF_IN: LP4.1 P2.14 R34.1
SPDIF_IN_2: C5.1 LP2.1 R127.2 U1.45(SPDIF_IN)
SS1P2: C38.1 U5.15(SS)
SWAP/POL: J17.2 U1.1(SWAP/POL)
SWAP_POL_HI: J17.1 R61.2
SWAP_POL_LO: J17.3 R62.1
TEST_A1: J7.2 U1.27(TEST/A1)
TPS3808_CT: C28.1 U3.4(CT)
TX_TERM_CTL: J14.2 U1.36(TX_TERM_CTL)
TX_TERM_CTL_HI: J14.1 R72.2
TX_TERM_CTL_LO: J14.3 R74.1
USB_5V: C39.1 C60.1 J13.1(VBUS) SW2.3 U16.1(VCC)
VSADJ: J8.2 U1.22(VSADJ)
X1: C51.1 U7.27(X1/CLKI) Y1.3
X2: C50.1 U7.26(X2) Y1.1
N16782838: R77.2 R78.2 U3.1(RESET#)
N16874758: J7.1 R66.2
N16874763: J7.3 R69.1
N16881139: J5.3(2) J6.3
N16881148: J4.3 J5.1
N16883754: J8.1 R75.2
N16883759: J8.3 R76.1(A) R76.2(WIPER) R115.1
N16887406: R102.2 U7.12(\\~{WAKEUP})
N16892757: Q1.1(G) R5.2 R12.2
N16892765: Q1.3(D) Q2.1(G) R11.1
N16892877: Q2.3(D) R13.1
N16906083: C5.2 C7.1 R36.2
N16910161: C4.2 C6.2 R35.2
N16916452: JP1.1 R122.1 U7.11(SCL)
N16916458: JP1.2 R100.2 R122.2 U8.6(SCL)
N16916991: R99.2 U7.10(SDA) U8.5(SDA)
N16919313: R94.1 U7.5(PUR)
N16919318: C45.1 R94.2 R96.1 U7.6(DP0)
N16919400: C49.2 R95.1 U7.7(DM0)
N16919998: R101.1 U7.1(\\~{VREGEN})
N16928867: C7.2 R34.2
N16962991: L2.2 U6.5(L)
N16965307: R83.1 R120.1 U4.7(FSW)
N16965311: L1.1 U4.1(SW1) U4.2(SW2) U4.3(SW3)
N16965335: C34.1 U4.9(SS/TR)
N16968702: R98.2 U7.23(TEST0) U7.24(TEST1)
N16982334: R121.1 U8.7(WP)
N17019193: R131.1 U1.4(HPD_SRC)
N17024118: J13.2(DM) R95.2 U16.5(IO2)
N17024121: J13.3(DP) R96.2 U16.3(IO1)
N17064614: D2.1(A) R82.1

Not connected (* = marked no-connect by the designer): D1 2*; J5 4(7)* 5(3)* 6(8)* 7(4)* 8(9)* 9(5)*; J13 4(ID)*; U1 18(NC) 40(NC)*; U7 2(SUSP)* 13(\\~{CTS})* 14(\\~{DSR})* 15(\\~{DCD})* 16(\\~{RI}/CP)* 17(SIN/IR_SIN)* 19(SOUT/IR_SOUT)* 20(\\~{RTS})* 21(\\~{DTR})* 22(CLKOUT)* 31(P3_1)* 32(P3_0)*; U16 2(NC)*

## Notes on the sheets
sheet 1
- INT028
sheet 2
- Pop C26 and depop
  R77 if not  using the
  Reset  SW.
- INT028
sheet 3
- NOTES:
  - 100-ohm differential impedance for HDMI differential pairs.
- BLOCK DIAGRAM
- USB2
  CONNECTOR
- 5V
  DONGLE
- 5V to 3.3V
  LDO
- AARDVARK
  CONNECTOR
- TUSB3410
- 3.3V to 1.2V
  LDO
- SCL_CTL
- SDA_CTL
- HDMI CONNECTOR BOTTOM
- IN0P/N
- TMDS_D2P/N
- HDMI CONNECTOR
- IN1P/N
- TMDS_D1P/N
- TMDS171
  (48-pin QFN)
- IN2P/N
- TMDS_D0P/N
- IN3P/N
- TMDS_CLKP/N
- AUXP/N
- DDC_SCL/SDA
- DDC - Snoop Only for TMDS171
- INT028
sheet 4
- 3.3V BUCK REGULATOR - 4V to 17V input
- 5.0V BOOST
- 1.2V LDO REGULATOR
- Note for TMDS1x1 products Board 1.1V is set to 1.2V
- INT028
sheet 5
- HDMI TX
- Pop 2K resistors on R45, R46 for TMDS171, DDC on
  Pop 47K resistors on R45, R46 for TMDS171, DDC snoop only
- INT028
sheet 6
- Note for TMDS1x1 products Board 1.1V is set to 1.2V
- Pop R131, no pop R129, R130 for HPD on
  No pop R131, pop R129, R130 for HPD snoop only
- INT028
sheet 7
- Three place switches - hi, lo, no connect
  Sampled at POR
- AARDVARK
  CONNECTOR
- INT028
sheet 8
- JP 1-2 NOT USED
  JP 2-3 for TMDS171
- HDMI RX
- Pop R16, R17, R24, R25. No pop R123, R124, R125, R126 - TMDS171, DDC on
  No pop R16, R17, R24, R25. Pop R123, R124, R125, R126 -  TMDS171, DDC snoop only
- Pop R104 if U6 is no pop
  No pop R104 if U6 is pop
- INT028
